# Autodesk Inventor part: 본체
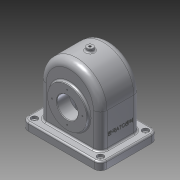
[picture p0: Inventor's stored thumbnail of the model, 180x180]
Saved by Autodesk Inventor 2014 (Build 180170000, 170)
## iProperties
Created: 2016-10
Part Number: 본체
Material: 알루미늄 6061
Document SubType Name: Modeling
Designer: USER
Density: 2.71 g/cm^3
Appearance: 알루미늄 - 평지
Mass: 1108.85 g
Surface Area: 1213 cm^2
Volume: 409.171 cm^3
Author: USER
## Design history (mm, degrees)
sketch "스케치1"
  geometry: L1 (-75, -55)-(75, -55); L2 (75, -55)-(75, 55); L3 (75, 55)-(-75, 55); L4 (-75, 55)-(-75, -55); L5 (-75, -55)-(75, 55); L6 (75, -55)-(-75, 55); 1 further point
  constraints: 12 end point, 2 midpoint, 2 parallel, 1 horizontal, 1 perpendicular
  dimensions: "d0" = 150 distance of L3.end L2.end; "d1" = 110 distance of L2.end L1.end
extrude "돌출1" new body sketch "스케치1" distance "d2" = 15; taper "d3" = 0 deg
sketch "스케치2"
  geometry: L1 (-75, 0)-(-75, 15) reference; L2 (-75, 15)-(75, 15) reference; L3 (75, 15)-(75, 0) reference; L4 (75, 0)-(-75, 0) reference; L5 (-58, 80)-(-58, 15); L6 (58, 80)-(58, 15); L7 (-58, 15)-(58, 15); C1 r 52 at (0, 80); A1 r 58 centre (0, 80) between (-58, 80) and (58, 80); 2 further points
  constraints: 6 end point, 2 centre point, 2 perpendicular, 2 point on circle, 2 point on line, 2 tangent, 1 coincident, 1 collinear, 1 horizontal alignment, 1 midpoint, 1 vertical alignment
  dimensions: "d5" = 104 diameter of C1; "d6" = 6 radial gap between concentric circles of A1 C1; "d9" = 80 distance from line of L4 C1.centre
extrude "돌출2" join sketch "스케치2" stored distance "d7" = 77; taper "d8" = 0 deg
sketch "스케치3"
  geometry: L1 (-75, 0)-(75, 0) reference; C1 r 37.5 at (0, 65); C2 r 20 at (0, 65); 2 further points
  constraints: 2 centre point, 1 coincident, 1 midpoint, 1 vertical alignment
  dimensions: "d10" = 75 diameter of C1; "d11" = 40 diameter of C2; "d14" = 65 distance from line of C1.centre L1
extrude "돌출3" join sketch "스케치3" distance "d12" = 5; taper "d13" = 0 deg
sketch "스케치4"
  geometry: L1 (58, -80)-(58, -15) reference; L2 (-58, -15)-(58, -15) reference; L3 (-58, -15)-(-58, -80) reference; A1 r 58 centre (0, -80) between (-58, -80) and (58, -80) reference; 1 further point
sketch "스케치5"
  geometry: L1 (75, 0)-(-75, 0) reference; C1 r 31 at (0, -65); C2 r 20 at (0, -65); 2 further points
  constraints: 2 centre point, 1 coincident, 1 midpoint, 1 vertical alignment
  dimensions: "d15" = 62 diameter of C1; "d16" = 40 diameter of C2; "d17" = 65 distance from line of L1 C1.centre
extrude "돌출4" join sketch "스케치5" distance "d18" = 10; taper "d19" = 0 deg
sketch "스케치6"
  geometry: C1 r 20 at (0, 0) reference; 1 further point
extrude "돌출5" cut sketch "스케치6" stored distance "d20" = 10; taper "d21" = 0 deg
sketch "스케치8"
  geometry: L1 (-43.5, 102.5)-(-38.5, 102.5) reference; L2 (-38.5, 102.5)-(-38.5, 138) reference; L3 (-38.5, 138)-(38.5, 138) reference; L4 (38.5, 138)-(38.5, 96) reference; L5 (38.5, 96)-(48.5, 96) reference; L6 (48.5, 96)-(48.5, 85) reference; L7 (48.5, 85)-(-43.5, 85) reference; L8 (-43.5, 85)-(-43.5, 102.5) reference; L9 (-55, 0)-(-55, 15) reference; L10 (-55, 15)-(-38.5, 15) reference; L11 (-38.5, 15)-(-38.5, 27.5) reference; L12 (-38.5, 27.5)-(-43.5, 27.5) reference; L13 (-43.5, 27.5)-(-43.5, 45) reference; L14 (-43.5, 45)-(48.5, 45) reference; L15 (48.5, 45)-(48.5, 34) reference; L16 (48.5, 34)-(38.5, 34) reference; L17 (38.5, 34)-(38.5, 15) reference; L18 (38.5, 15)-(55, 15) reference; L19 (55, 15)-(55, 0) reference; L20 (55, 0)-(-55, 0) reference; L21 (-44.653, 80)-(48.5, 80); L22 (-33.5, 85)-(-33.5, 133); L23 (-33.5, 133)-(33.5, 133); L24 (33.5, 133)-(33.5, 85); 1 further point
  constraints: 8 end point, 3 perpendicular, 2 point on line, 1 parallel
  dimensions: "d28" = 80 distance between parallel lines of L20 L21; "d29" = 5 distance between parallel lines of L2 L22; "d30" = 5 distance between parallel lines of L3 L23; "d31" = 5 distance between parallel lines of L4 L24
revolve "회전1" sketch "스케치8" stored, may be unused: angle "d32" = 90 deg
sketch "스케치9"
  geometry: L1 (75, -55)-(-75, -55) reference; L2 (75, 55)-(75, -55) reference; L3 (-75, 55)-(75, 55) reference; L4 (-75, -55)-(-75, 55) reference; 1 further point
node "작업 평면1"
sketch "스케치10"
  geometry: L1 (-34.369, -43.5)-(-34.369, -38.5) reference; L2 (-34.369, -38.5)-(-58, -38.5) reference; L3 (-58, -38.5)-(-58, 38.5) reference; L4 (-58, 38.5)-(-27.129, 38.5) reference; L5 (-27.129, 38.5)-(-27.129, 48.5) reference; L6 (-27.129, 48.5)-(-13.229, 48.5) reference; L7 (-13.229, 48.5)-(-13.229, 33.5) reference; L8 (-13.229, 33.5)-(-53, 33.5) reference; L9 (-53, 33.5)-(-53, -33.5) reference; L10 (-53, -33.5)-(-13.229, -33.5) reference; L11 (-13.229, -33.5)-(-13.229, -43.5) reference; L12 (-13.229, -43.5)-(-34.369, -43.5) reference; L13 (34.369, -38.5)-(34.369, -43.5) reference; L14 (34.369, -43.5)-(13.229, -43.5) reference; L15 (13.229, -43.5)-(13.229, -33.5) reference; L16 (13.229, -33.5)-(53, -33.5) reference; L17 (53, -33.5)-(53, 33.5) reference; L18 (53, 33.5)-(13.229, 33.5) reference; L19 (13.229, 33.5)-(13.229, 48.5) reference; L20 (13.229, 48.5)-(27.129, 48.5) reference; L21 (27.129, 48.5)-(27.129, 38.5) reference; L22 (27.129, 38.5)-(58, 38.5) reference; L23 (58, 38.5)-(58, -38.5) reference; L24 (58, -38.5)-(34.369, -38.5) reference; L25 (-13.229, 33.5)-(13.229, 33.5); L26 (13.229, -33.5)-(-13.229, -33.5); 1 further point
  constraints: 4 end point, 2 collinear
extrude "돌출6" cut sketch "스케치10" distance "d34" = 80; taper "d35" = 0 deg
sketch "스케치11"
  geometry: L1 (-43.5, 102.5)-(-38.5, 102.5) reference; L2 (-38.5, 102.5)-(-38.5, 138) reference; L3 (-38.5, 138)-(38.5, 138) reference; L4 (38.5, 138)-(38.5, 96) reference; L5 (38.5, 96)-(48.5, 96) reference; L6 (48.5, 96)-(48.5, 85) reference; L7 (48.5, 85)-(33.5, 85) reference; L8 (33.5, 85)-(33.5, 133) reference; L9 (33.5, 133)-(-33.5, 133) reference; L10 (-33.5, 133)-(-33.5, 85) reference; L11 (-33.5, 85)-(-43.5, 85) reference; L12 (-43.5, 85)-(-43.5, 102.5) reference; L13 (55, 15)-(55, 0) reference; L14 (55, 0)-(33.5, 0) reference; L15 (33.5, 0)-(33.5, 45) reference; L16 (33.5, 45)-(48.5, 45) reference; L17 (48.5, 45)-(48.5, 34) reference; L18 (48.5, 34)-(38.5, 34) reference; L19 (38.5, 34)-(38.5, 15) reference; L20 (38.5, 15)-(55, 15) reference; L21 (-55, 0)-(-55, 15) reference; L22 (-55, 15)-(-38.5, 15) reference; L23 (-38.5, 15)-(-38.5, 27.5) reference; L24 (-38.5, 27.5)-(-43.5, 27.5) reference; L25 (-43.5, 27.5)-(-43.5, 45) reference; L26 (-43.5, 45)-(-33.5, 45) reference; L27 (-33.5, 45)-(-33.5, 0) reference; L28 (-33.5, 0)-(-55, 0) reference; L29 (-33.5, 85)-(-19.5, 85); L30 (-19.5, 85)-(-19.5, 93); L31 (-19.5, 93)-(-33.5, 104.747); L32 (-43.5, 85)-(-43.5, 45); L33 (48.5, 85)-(48.5, 45); L34 (-43.5, 65)-(48.5, 65); 1 further point
  constraints: 12 end point, 2 collinear, 2 midpoint, 1 parallel, 1 perpendicular, 1 point on line
  dimensions: "d36" = 24 distance of L11.end L29.end; "d37" = 8 distance of L29.end L30.end; "d38" = 50 deg angle of L30 L31
revolve "회전2" sketch "스케치11" stored, may be unused: angle "d39" = 90 deg
node "작업 평면2"
sketch "스케치12"
  geometry: L1 (58, 38.5)-(-58, 38.5) reference; L2 (58, 38.5)-(58, -38.5) reference; L3 (-58, -38.5)-(-58, 38.5) reference; L4 (-58, -38.5)-(58, -38.5) reference; C1 r 6 at (0, 0); 1 further point
  constraints: 1 centre point, 1 coincident
  dimensions: "d41" = 12 diameter of C1
extrude "돌출7" join sketch "스케치12" stored distance "d42" = 80; taper "d43" = 0 deg
sketch "스케치13"
  geometry: C1 r 6 at (0, 0) reference; 2 further points
  constraints: 2 coincident
hole "구멍1" sketch "스케치13" at (0, 0) diameter "d44" = 4.134; stored, may be unused: countersink angle "d48" = 90 deg, drill point angle "d50" = 118 deg; dims "d45" = 18, "d46" = 4, "d47" = 2, "d49" = 20
sketch "스케치14"
  geometry: C1 r 20 at (0, 0) reference; C2 r 37.5 at (0, 0) reference; A1 r 29 centre (0, 0) between (0, 29) and (29, 0); 3 further points
  constraints: 4 point on circle, 2 horizontal alignment, 2 vertical alignment, 1 centre point, 1 coincident
  dimensions: "d51" = 58 diameter of A1
hole "구멍2" sketch "스케치14" at (0, 29), (29, 0), (0, -29), (-29, 0) diameter "d52" = 2.459; stored, may be unused: countersink angle "d56" = 90 deg, drill point angle "d58" = 118 deg; dims "d53" = 6, "d54" = 4, "d55" = 2, "d57" = 8
sketch "스케치15"
  geometry: C1 r 20 at (0, 0) reference; C2 r 31 at (0, 0) reference; A1 r 26 centre (0, 0) between (0, 26) and (26, 0); 3 further points
  constraints: 4 point on circle, 2 horizontal alignment, 2 vertical alignment, 1 centre point, 1 coincident
  dimensions: "d59" = 52 diameter of A1
hole "구멍3" sketch "스케치15" at (0, 26), (26, 0), (0, -26), (-26, 0) diameter "d60" = 2.459; stored, may be unused: countersink angle "d64" = 90 deg, drill point angle "d66" = 118 deg; dims "d61" = 6, "d62" = 4, "d63" = 2, "d65" = 8
fillet "모깎기1" dims "d67" = 13
fillet "모깎기2" dims "d68" = 3
fillet "모깎기3" dims "d69" = 3, "d70" = 12
fillet "모깎기4" dims "d71" = 3
sketch "스케치16"
  geometry: C1 r 6 at (-63, 43); C2 r 6 at (-63, -43); C3 r 6 at (63, -43); C4 r 6 at (63, 43); A1 r 12 centre (-63, -43) between (-75, -43) and (-63, -55) reference; A2 r 12 centre (63, -43) between (63, -55) and (75, -43) reference; A3 r 12 centre (63, 43) between (75, 43) and (63, 55) reference; A4 r 12 centre (-63, 43) between (-63, 55) and (-75, 43) reference; 1 further point
  constraints: 4 centre point, 4 coincident
  dimensions: "d72" = 12 diameter of C1; "d73" = 12 diameter of C2; "d74" = 12 diameter of C3; "d75" = 12 diameter of C4
extrude "돌출8" cut sketch "스케치16" distance "d76" = 5; taper "d77" = 0 deg
sketch "스케치17"
  geometry: L1 (-12, 0)-(-12, 86) reference; L2 (0, 98)-(126, 98) reference; L3 (138, 86)-(138, 0) reference; L4 (126, -12)-(0, -12) reference; L5 (116, 9.5)-(116, 76.5) reference; L6 (116, 76.5)-(10, 76.5) reference; L7 (10, 76.5)-(10, 9.5) reference; L8 (10, 9.5)-(116, 9.5) reference; C1 r 6 at (0, 0) reference; C2 r 2.5 at (0, 0); C3 r 6 at (126, 0) reference; C4 r 6 at (0, 86) reference; C5 r 6 at (0, 0) reference; C6 r 6 at (126, 86) reference; C7 r 2.5 at (0, 86); C8 r 2.5 at (126, 0); C9 r 2.5 at (126, 86); A1 r 12 centre (0, 0) between (-12, 0) and (0, -12) reference; A2 r 12 centre (0, 86) between (0, 98) and (-12, 86) reference; A3 r 12 centre (126, 86) between (138, 86) and (126, 98) reference; A4 r 12 centre (126, 0) between (126, -12) and (138, 0) reference; 1 further point
  constraints: 4 centre point, 4 coincident
  dimensions: "d78" = 5 diameter of C2; "d79" = 5 diameter of C7; "d80" = 5 diameter of C8; "d81" = 5 diameter of C9
extrude "돌출9" cut sketch "스케치17" stored distance "d82" = 5; taper "d83" = 0 deg
sketch "스케치18"
  geometry: L1 (80, -17.5)-(80, 68.5) reference; L2 (0, -13)-(62, -13) reference; 2 further points
  constraints: 1 other
  dimensions: "d84" = 40 distance from line of L1 point (40, 25.5); "d85" = 38.5 distance from line of point (40, 25.5) L2
feature "엠보싱1" sketch "스케치18" dims "d0" = 150, "d1" = 110, "d86" = 0.5, "d87" = 0
fillet "모깎기5" dims "d88" = 3, "d89" = 8
chamfer "모따기1" distance "d90" = 1; stored, may be unused: second distance "d91" = 2, angle "d92" = 45 deg
fillet "모깎기6" dims "d93" = 3
node "솔리드1"
node "절단 모서리 투영1"
node "절단 모서리 투영3"
node "절단 모서리 투영4"
node "절단 모서리 투영5"
node "절단 모서리 투영6"
other parameters: "d40" = 144
